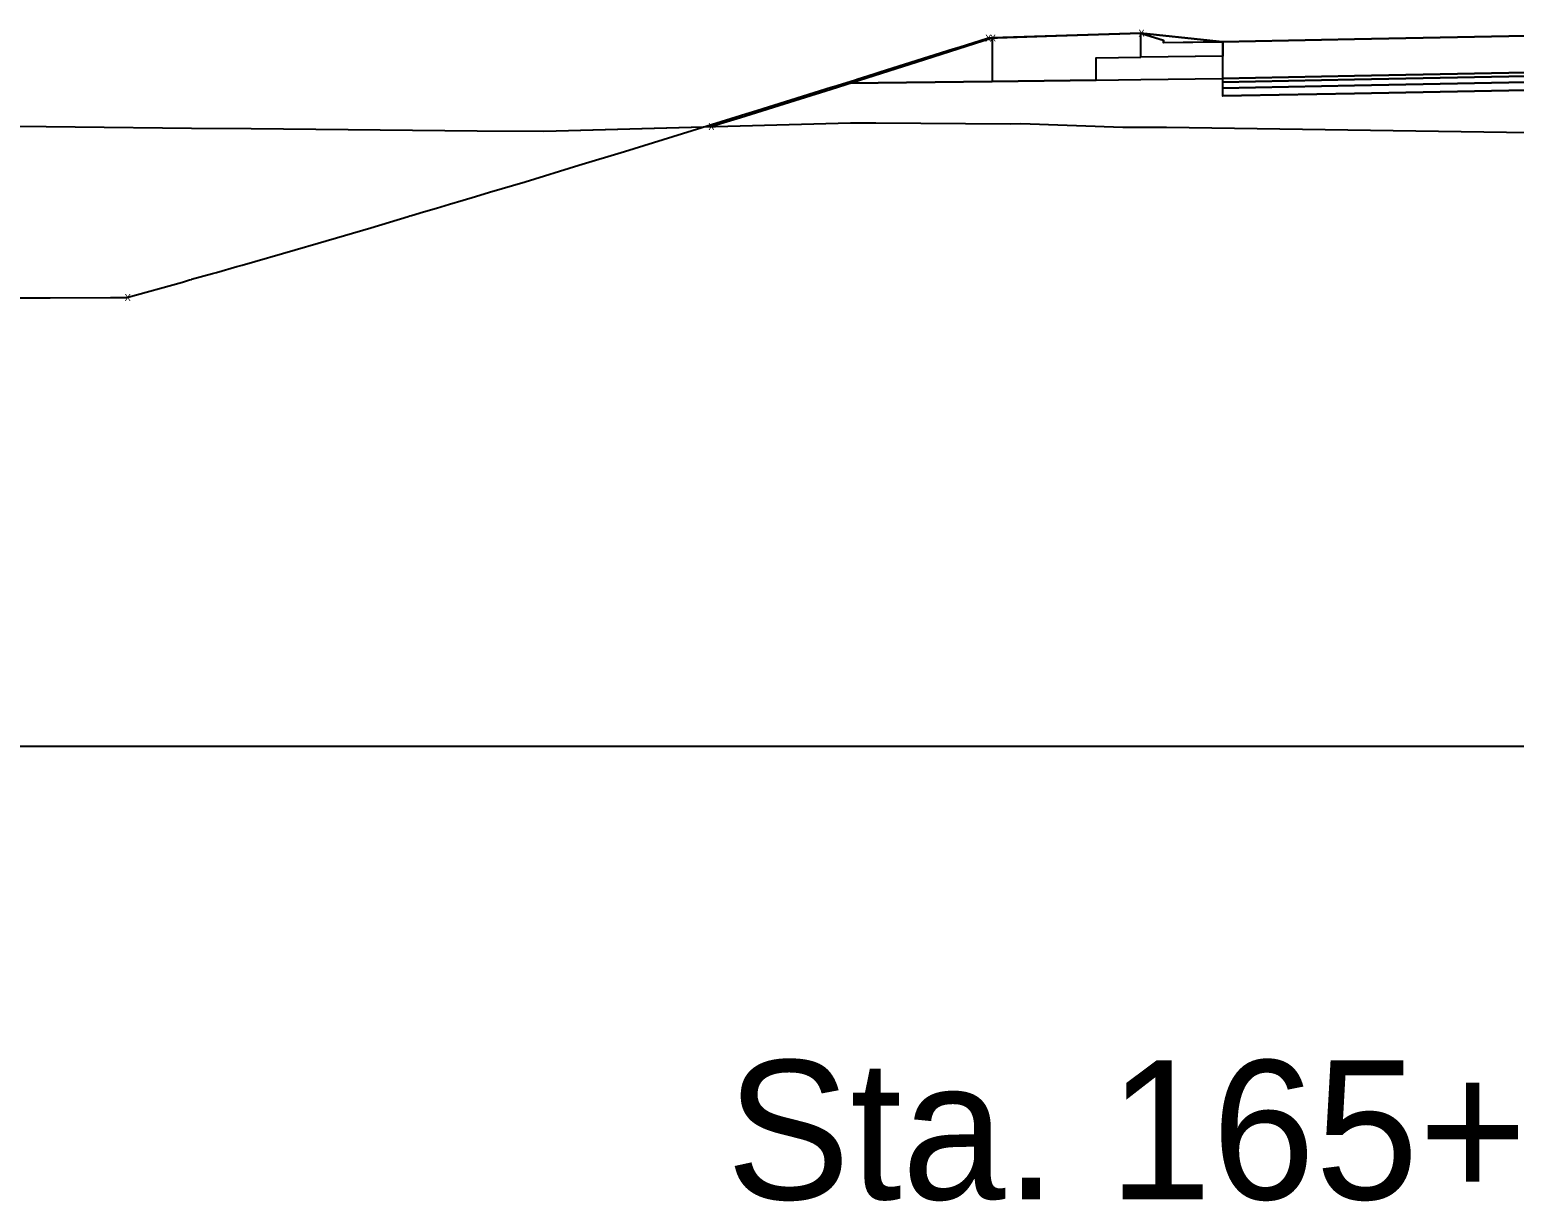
# Model space of a CAD drawing. Extents: x -26 to 303, y -16 to 6048.
# Drawn here: x 87.7 to 138.9, y 4984.3 to 5024.7 of the extents above; entities that cross this region are included whole.
import ezdxf

# ---------------------------------------------------------------- set-up
doc = ezdxf.new("R2010")
doc.units = 0
for name, color, linetype in [('ASPHALT_19MM1', 7, 'Continuous'), ('ASPHALT_9_5MM1', 7, 'Continuous'), ('CONST_DCH', 7, 'Continuous'), ('CONST_LV3', 7, 'Continuous'), ('Default', 7, 'Continuous'), ('Draft_XS_Text', 7, 'Continuous'), ('DTM_P_FINISHED_GRADE', 7, 'Continuous'), ('DTM_P_FINISHED_GRADE2', 7, 'Continuous'), ('DTM_TEMP_DROP', 7, 'Continuous'), ('DTM_X_GROUND', 7, 'Continuous'), ('TRANS_PAVED_SHOULDERS', 7, 'Continuous'), ('X_PROFILES_1', 7, 'Continuous'), ('XS_CELL', 7, 'Continuous'), ('XS_M_SHAPES_EARTHWORK', 7, 'Continuous'), ('XS_P_ASPHALT', 7, 'Continuous'), ('XS_P_CONCRETE', 7, 'Continuous'), ('XS_P_GROUND', 7, 'Continuous'), ('XS_P_SHOULDER', 7, 'Continuous'), ('XS_P_SUBGRADE_GRANULAR', 7, 'Continuous'), ('XS_P_SUBGRADE_GRANULAR_B', 7, 'Continuous')]:
    doc.layers.add(name, color=color, linetype=linetype)

msp = doc.modelspace()

# ---------------------------------------------------------------- linework, layer by layer
at = {"layer": 'ASPHALT_19MM1'}
msp.add_lwpolyline([(128.86, 5022.726), (128.86, 5022.455), (133.416, 5022.543), (150, 5022.869), (157.477, 5022.723), (171.377, 5022.471), (171.377, 5022.742), (157.477, 5022.994), (150, 5023.14), (133.416, 5022.814), (128.86, 5022.726)], dxfattribs=at)
at = {"layer": 'ASPHALT_9_5MM1'}
msp.add_lwpolyline([(128.86, 5023.059), (128.86, 5022.934), (133.416, 5023.022), (150, 5023.348), (157.477, 5023.202), (171.377, 5022.95), (171.377, 5023.075), (157.477, 5023.327), (150, 5023.473), (133.416, 5023.147), (128.86, 5023.059)], dxfattribs=at)
at = {"layer": 'CONST_LV3'}
for points in [[(91.013, 5015.493), (92.93, 5016.031), (93.175, 5016.102), (93.242, 5016.121), (93.251, 5016.124), (93.976, 5016.324), (94.112, 5016.364), (94.815, 5016.564), (94.99, 5016.615), (96.829, 5017.14), (97.617, 5017.374), (99.44, 5017.906), (100.726, 5018.294), (100.788, 5018.313), (100.839, 5018.328), (100.844, 5018.33), (100.849, 5018.331), (101.259, 5018.451), (101.625, 5018.561), (101.666, 5018.573), (101.705, 5018.585), (102.162, 5018.718), (102.629, 5018.858), (103.053, 5018.984), (103.544, 5019.133), (104.765, 5019.496), (106.629, 5020.067), (108.204, 5020.542), (112.205, 5021.785), (112.212, 5021.787), (112.244, 5021.797), (112.774, 5021.958), (115.337, 5022.757), (115.432, 5022.785), (116.177, 5023.018), (116.239, 5023.037), (116.828, 5023.222), (117.033, 5023.284), (119.558, 5024.079), (119.755, 5024.14), (120.738, 5024.453), (123.796, 5024.551), (126.04, 5024.627)], [(111.175, 5021.398), (111.632, 5021.538), (112.206, 5021.716), (114.27, 5022.36), (115.338, 5022.696), (118.567, 5023.716), (120.897, 5024.458), (123.825, 5024.554), (126.03, 5024.625)], [(126.04, 5024.627), (120.738, 5024.453)], [(128.866, 5024.333), (128.866, 5023.833), (126.04, 5023.794), (126.04, 5024.627), (126.814, 5024.388), (126.816, 5024.304), (128.866, 5024.333)], [(128.86, 5024.33), (128.86, 5023.059), (133.416, 5023.147), (150, 5023.473), (157.477, 5023.327), (171.377, 5023.075), (171.377, 5024.346), (157.477, 5024.598), (150, 5024.744), (133.416, 5024.418), (128.86, 5024.33)], [(124.491, 5023), (124.49, 5023.771), (126.03, 5023.791)]]:
    msp.add_lwpolyline(points, dxfattribs=at)
at = {"layer": 'Default'}
msp.add_lwpolyline([(128.866, 5024.333), (131.709, 5024.388), (132.002, 5024.394), (150, 5024.744), (170.108, 5024.368), (171.334, 5024.346)], dxfattribs=at)
msp.add_lwpolyline([(128.866, 5022.455), (128.866, 5024.333), (131.709, 5024.388), (132.002, 5024.394), (150, 5024.744), (170.108, 5024.368), (171.334, 5024.346), (171.334, 5022.472), (157.477, 5022.723), (150, 5022.869), (133.416, 5022.543)], close=True, dxfattribs=at)
at = {"layer": 'DTM_P_FINISHED_GRADE'}
msp.add_lwpolyline([(128.86, 5024.33), (133.416, 5024.418), (150, 5024.744), (157.477, 5024.598), (171.377, 5024.346)], dxfattribs=at)
at = {"layer": 'DTM_P_FINISHED_GRADE2'}
msp.add_lwpolyline([(111.175, 5021.398), (111.632, 5021.538), (112.206, 5021.716), (114.27, 5022.36), (115.338, 5022.696), (118.567, 5023.716), (120.897, 5024.458), (123.127, 5024.528), (126.03, 5024.625), (126.237, 5024.56), (126.805, 5024.385), (126.806, 5024.322), (126.807, 5024.302), (128.56, 5024.326), (128.86, 5024.33), (133.416, 5024.418), (150, 5024.744)], dxfattribs=at)
at = {"layer": 'DTM_X_GROUND'}
for points in [[(85.193, 5021.433), (93.24, 5021.339), (95.309, 5021.337), (103.109, 5021.249), (105.41, 5021.246), (110.942, 5021.394), (111.175, 5021.398), (111.632, 5021.538), (112.206, 5021.716), (114.27, 5022.36), (115.338, 5022.696), (118.567, 5023.716), (120.897, 5024.458), (123.127, 5024.528), (126.03, 5024.625), (128.42, 5024.376), (128.86, 5024.33), (133.416, 5024.418), (150, 5024.744)], [(85.193, 5021.433), (93.24, 5021.339), (95.309, 5021.337), (103.109, 5021.249), (105.41, 5021.246), (116.009, 5021.53), (116.57, 5021.527), (116.885, 5021.525), (121.536, 5021.488), (121.891, 5021.503), (125.408, 5021.384), (126.925, 5021.382), (138.671, 5021.203), (142.371, 5021.197)]]:
    msp.add_lwpolyline(points, dxfattribs=at)
at = {"layer": 'TRANS_PAVED_SHOULDERS'}
msp.add_lwpolyline([(128.86, 5022.934), (128.86, 5022.726), (133.416, 5022.814), (150, 5023.14), (157.477, 5022.994), (171.377, 5022.742), (171.377, 5022.95), (157.477, 5023.202), (150, 5023.348), (133.416, 5023.022), (128.86, 5022.934)], dxfattribs=at)
at = {"layer": 'XS_CELL'}
msp.add_line((0, 5000), (150, 5000), dxfattribs=at)
at = {"layer": 'XS_M_SHAPES_EARTHWORK'}
msp.add_lwpolyline([(128.866, 5024.33), (128.86, 5024.33), (128.42, 5024.376), (126.03, 5024.625), (123.127, 5024.528), (120.897, 5024.458), (118.567, 5023.716), (115.968, 5022.895), (120.898, 5022.954), (124.491, 5023), (126.03, 5023.021), (128.86, 5023.059), (128.86, 5022.934), (128.86, 5022.726), (128.86, 5022.455), (128.866, 5022.455)], close=True, dxfattribs=at)
at = {"layer": 'XS_P_ASPHALT'}
msp.add_lwpolyline([(128.86, 5024.33), (133.416, 5024.418), (150, 5024.744), (157.477, 5024.598), (171.377, 5024.346)], dxfattribs=at)
at = {"layer": 'XS_P_CONCRETE'}
msp.add_lwpolyline([(128.86, 5024.33), (128.86, 5023.83), (126.03, 5023.791), (126.03, 5024.625), (126.805, 5024.385), (126.807, 5024.302), (128.86, 5024.33)], dxfattribs=at)
at = {"layer": 'XS_P_GROUND'}
for points in [[(91.013, 5015.493), (92.93, 5016.031), (93.175, 5016.102), (93.242, 5016.121), (93.251, 5016.124), (93.976, 5016.324), (94.112, 5016.364), (94.815, 5016.564), (94.99, 5016.615), (96.829, 5017.14), (97.617, 5017.374), (99.44, 5017.906), (100.726, 5018.294), (100.788, 5018.313), (100.839, 5018.328), (100.844, 5018.33), (100.849, 5018.331), (101.259, 5018.451), (101.625, 5018.561), (101.666, 5018.573), (101.705, 5018.585), (102.162, 5018.718), (102.629, 5018.858), (103.053, 5018.984), (103.544, 5019.133), (104.765, 5019.496), (106.629, 5020.067), (108.204, 5020.542), (112.205, 5021.785), (112.212, 5021.787), (112.244, 5021.797), (112.774, 5021.958), (115.337, 5022.757), (115.432, 5022.785), (116.177, 5023.018), (116.239, 5023.037), (116.828, 5023.222), (117.033, 5023.284), (119.558, 5024.079), (119.755, 5024.14), (120.738, 5024.453)], [(111.175, 5021.398), (111.632, 5021.538), (112.206, 5021.716), (114.27, 5022.36), (115.338, 5022.696), (118.567, 5023.716), (120.897, 5024.458)], [(63.537, 5015.541), (64.873, 5015.549), (65.795, 5015.554), (66.365, 5015.558), (67.875, 5015.567), (68.156, 5015.526), (68.943, 5015.41), (69.204, 5015.411), (69.957, 5015.416), (70.184, 5015.417), (70.854, 5015.421), (72.135, 5015.429), (75.912, 5015.452), (76.453, 5015.455), (78.35, 5015.467), (78.893, 5015.47), (80.971, 5015.482), (81.944, 5015.483), (86.029, 5015.488), (88.36, 5015.49), (90.445, 5015.493), (90.996, 5015.493), (91.013, 5015.493)]]:
    msp.add_lwpolyline(points, dxfattribs=at)
at = {"layer": 'XS_P_SHOULDER'}
msp.add_lwpolyline([(126.03, 5024.625), (120.897, 5024.458)], dxfattribs=at)
at = {"layer": 'XS_P_SUBGRADE_GRANULAR'}
for points in [[(128.86, 5023.059), (133.416, 5023.147), (150, 5023.473), (157.477, 5023.327), (171.377, 5023.075)], [(124.491, 5023), (126.03, 5023.021)], [(126.03, 5023.021), (128.86, 5023.059)]]:
    msp.add_lwpolyline(points, dxfattribs=at)
at = {"layer": 'XS_P_SUBGRADE_GRANULAR_B'}
for points in [[(120.897, 5024.458), (120.897, 5023.561), (120.898, 5022.954)], [(120.898, 5022.954), (115.967, 5022.895)], [(124.491, 5023), (120.898, 5022.954)]]:
    msp.add_lwpolyline(points, dxfattribs=at)

# ---------------------------------------------------------------- texts
at = {"layer": 'CONST_DCH'}
msp.add_text('X', height=0.24, dxfattribs=at).set_placement((90.935, 5015.373))
at = {"layer": 'Draft_XS_Text'}
msp.add_text('Sta. 165+50.0000 R1', height=4.8, dxfattribs=at).set_placement((111.716, 4984.35))
at = {"layer": 'DTM_TEMP_DROP'}
for p in [(111.096, 5021.278), (90.935, 5015.373)]:
    msp.add_text('X', height=0.24, dxfattribs=at).set_placement(p)
at = {"layer": 'X_PROFILES_1'}
msp.add_text('X', height=0.24, dxfattribs=at).set_placement((120.66, 5024.333))
at = {"layer": 'XS_P_GROUND'}
for p in [(120.818, 5024.338), (125.952, 5024.505)]:
    msp.add_text('X', height=0.24, dxfattribs=at).set_placement(p)
at = {"layer": 'XS_P_SUBGRADE_GRANULAR'}
msp.add_text('X', height=0.24, dxfattribs=at).set_placement((111.096, 5021.278))

doc.saveas('drawing.dxf')
